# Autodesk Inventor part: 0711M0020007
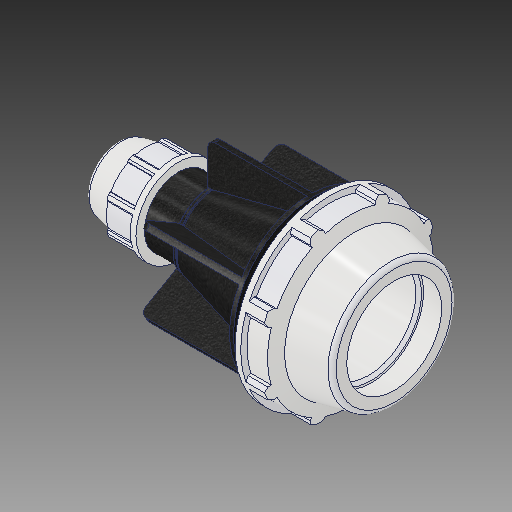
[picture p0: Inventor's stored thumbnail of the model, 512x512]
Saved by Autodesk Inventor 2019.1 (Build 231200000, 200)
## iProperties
Created: 2017-02
Part Number: 0711M0020007
Material: PVC-Piping
Description: PLASSON REDUCING COUPLER 2'' - 3/4''
Document SubType Name: Modeling
Designer: KIM
Mass: 92.6774 g
Surface Area: 199.44 cm^2
Volume: 66.1981 cm^3
Density: 1.4 g/cm^3
Appearance: PTFE
Author: KIM
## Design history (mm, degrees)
derived "0711M0.ipt"
feature "Solid1::0711M0.ipt"
tag "TaggingFeature1"
body "Solid1"
other parameters: "d2" = 60.1, "d4" = 14.58333, "d5" = 25, "d7" = 113.03, "d9" = 25, "d11" = 2.5, "d12" = 90.424, "d13" = 120 deg, "d14" = 78.13, "d15" = 12 deg, "d16" = 101.727, "d18" = 3.005, "d19" = 35 deg, "d20" = 17.5 deg, "d21" = 105.1179, "d23" = 0, "d25" = 360 deg, "d27" = 2.2606, "d42" = 19.25, "d46" = 1.803, "d51" = 175, "d52" = 60.34483, "d53" = 12 deg, "d54" = 54.102, "d56" = 39.9, "d57" = 26.6, "d58" = 54.09, "d59" = 23.94, "d60" = 48.6918, "d61" = 43.2816, "d62" = 17.5, "d63" = 21, "d64" = 120 deg, "d65" = 54.102, "d68" = 12.5, "d74" = 50.31486, "d75" = 35 deg, "d76" = 17.5 deg, "d78" = 0, "d80" = 360 deg, "d85" = 1.08204, "d88" = 0.532, "d93" = 62, "d94" = 79.121, "d97" = 3.7285, "d98" = 3.6068, "d99" = 0, "d100" = 4.5212, "d102" = 360 deg, "d104" = 2, "d106" = 0, "d107" = 3.6068, "d108" = 0, "d109" = 3.6068, "d110" = 0, "d_" = 60.1, "E_" = 113.03, "H_" = 175, "l_" = 54.102, "d_1" = 26.6, "E_1" = 54.102, "l_1" = 62, "d96" = 11.1855
